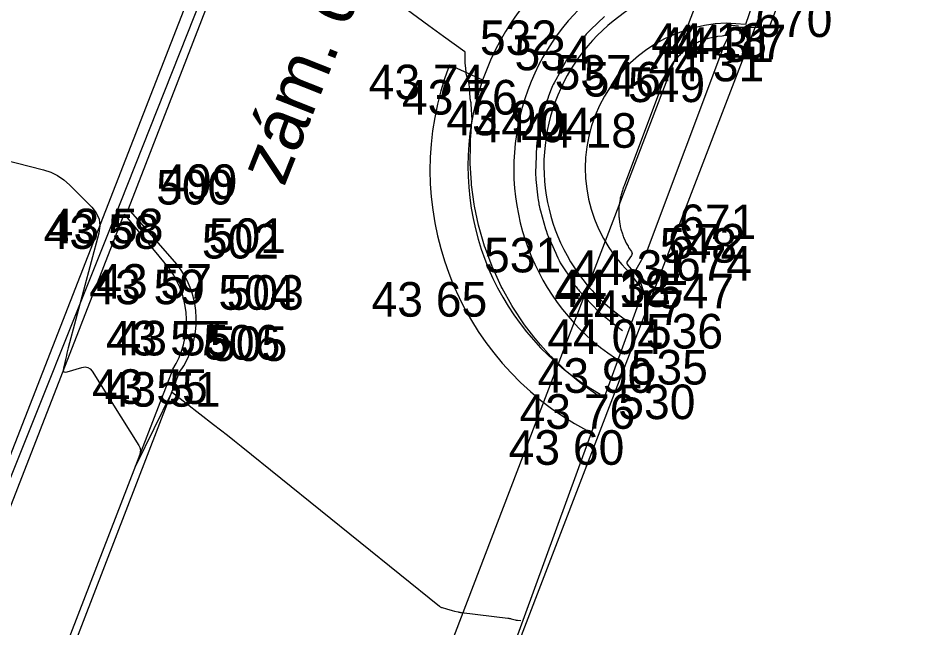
# Model space of a CAD drawing. Extents: x -702257 to -701487, y -1009871 to -1008841.
# Drawn here: x -701671.59 to -701664.97, y -1009088.46 to -1009084.05 of the extents above; entities that cross this region are included whole.
import ezdxf

# ---------------------------------------------------------------- set-up
doc = ezdxf.new("R2010")
doc.units = 0
for name, color, linetype in [('Ex_Major Contours', 7, 'Continuous'), ('Ex_Minor Contours', 7, 'Continuous'), ('Z_betonova_konstrukce', 7, 'Continuous'), ('Z_body', 7, 'Continuous'), ('Z_body_cisla', 7, 'Continuous'), ('Z_body_vysky_redukovane', 7, 'Continuous'), ('Z_budova', 7, 'Continuous'), ('Z_katastr_hranice', 7, 'Continuous'), ('Z_katastr_vnitrni_kresba', 7, 'Continuous'), ('Z_komunikace', 7, 'Continuous'), ('Z_obruba', 7, 'Continuous'), ('Z_popisy', 7, 'Continuous'), ('Z_vstupy', 7, 'Continuous')]:
    doc.layers.add(name, color=color, linetype=linetype)

# ---------------------------------------------------------------- blocks, each defined once
blk = doc.blocks.new('POINT_DISPLAY')
blk.add_line((0, 0), (0, 0))

msp = doc.modelspace()

# ---------------------------------------------------------------- linework, layer by layer
at = {"layer": 'Ex_Major Contours'}
msp.add_lwpolyline([(-701667.3501, -1009084.0429), (-701667.4478, -1009084.1354), (-701667.458, -1009084.1454), (-701667.4748, -1009084.1623), (-701667.4813, -1009084.1691), (-701667.4875, -1009084.1762), (-701667.5026, -1009084.1943), (-701667.5114, -1009084.2054), (-701667.5922, -1009084.3109), (-701667.6006, -1009084.3222), (-701667.6141, -1009084.3412), (-701667.6193, -1009084.3489), (-701667.624, -1009084.357), (-701667.6546, -1009084.413), (-701667.6634, -1009084.4291), (-701667.7136, -1009084.5217), (-701667.7192, -1009084.5325), (-701667.7245, -1009084.5434), (-701667.7294, -1009084.5544), (-701667.7339, -1009084.5657), (-701667.7538, -1009084.6171), (-701667.7601, -1009084.6336), (-701667.7662, -1009084.6501), (-701667.7803, -1009084.6891), (-701667.784, -1009084.6999), (-701667.7875, -1009084.7108), (-701667.7941, -1009084.7326), (-701667.7972, -1009084.7436), (-701667.7997, -1009084.7547), (-701667.8287, -1009084.9007), (-701667.8356, -1009084.9353), (-701667.8372, -1009084.944), (-701667.8384, -1009084.9527), (-701667.8393, -1009084.9614), (-701667.8398, -1009084.9702), (-701667.8464, -1009085.1186), (-701667.8484, -1009085.1641), (-701667.8486, -1009085.1735), (-701667.8482, -1009085.1828), (-701667.8464, -1009085.2061), (-701667.845, -1009085.22), (-701667.8302, -1009085.3521), (-701667.8284, -1009085.3661), (-701667.8248, -1009085.3894), (-701667.8232, -1009085.3987), (-701667.8212, -1009085.4079), (-701667.8156, -1009085.4311), (-701667.812, -1009085.4449), (-701667.7759, -1009085.5745), (-701667.7718, -1009085.5882), (-701667.7645, -1009085.6109), (-701667.7612, -1009085.6199), (-701667.7575, -1009085.6286), (-701667.7012, -1009085.7508), (-701667.6954, -1009085.7639), (-701667.6862, -1009085.7859), (-701667.6823, -1009085.7946), (-701667.6781, -1009085.8031), (-701667.6694, -1009085.8199), (-701667.6648, -1009085.8282), (-701667.6597, -1009085.8363), (-701667.5857, -1009085.9465), (-701667.578, -1009085.9583), (-701667.5654, -1009085.9784), (-701667.5603, -1009085.9862), (-701667.5549, -1009085.9938), (-701667.5437, -1009086.0088), (-701667.5379, -1009086.0162), (-701667.5318, -1009086.0232), (-701667.45, -1009086.1114), (-701667.4313, -1009086.1315), (-701667.3999, -1009086.1647), (-701667.3935, -1009086.1712), (-701667.3869, -1009086.1775), (-701667.3801, -1009086.1836), (-701667.373, -1009086.1894), (-701667.2895, -1009086.2558), (-701667.2687, -1009086.2722), (-701667.22, -1009086.31)], dxfattribs=at)
at = {"layer": 'Ex_Minor Contours'}
for points in [[(-701667.3863, -1009086.7863), (-701667.3962, -1009086.7807), (-701667.3986, -1009086.7792), (-701667.5071, -1009086.7018), (-701667.514, -1009086.6971), (-701667.6237, -1009086.6058), (-701667.631, -1009086.5988), (-701667.7307, -1009086.503), (-701667.7369, -1009086.4965), (-701667.8121, -1009086.4128), (-701667.8243, -1009086.399), (-701667.8362, -1009086.385), (-701667.8478, -1009086.3708), (-701667.8592, -1009086.3564), (-701667.9268, -1009086.2691), (-701667.9331, -1009086.2605), (-701668.012, -1009086.1412), (-701668.0195, -1009086.1291), (-701668.0886, -1009086.0052), (-701668.0959, -1009085.991), (-701668.1552, -1009085.863), (-701668.1616, -1009085.8475), (-701668.2105, -1009085.7171), (-701668.2162, -1009085.6997), (-701668.2552, -1009085.5659), (-701668.2594, -1009085.549), (-701668.2884, -1009085.412), (-701668.2909, -1009085.3966), (-701668.31, -1009085.2569), (-701668.3111, -1009085.244), (-701668.32, -1009085.1033), (-701668.3201, -1009085.0971), (-701668.3196, -1009085.0846), (-701668.319, -1009084.9796), (-701668.3187, -1009084.9616), (-701668.3181, -1009084.9436), (-701668.3172, -1009084.9256), (-701668.316, -1009084.9077), (-701668.3074, -1009084.7964), (-701668.3068, -1009084.7906), (-701668.3126, -1009084.6716), (-701668.3134, -1009084.6647), (-701668.3149, -1009084.6578), (-701668.319, -1009084.6443), (-701668.3206, -1009084.6375), (-701668.3214, -1009084.6305), (-701668.3261, -1009084.5485), (-701668.327, -1009084.5388), (-701668.3283, -1009084.5293), (-701668.3303, -1009084.5198), (-701668.3327, -1009084.5104), (-701668.3484, -1009084.4567), (-701668.3493, -1009084.4521), (-701668.3502, -1009084.4426), (-701668.3542, -1009084.3952), (-701668.3553, -1009084.3793), (-701668.357, -1009084.3454), (-701668.3571, -1009084.3355), (-701668.357, -1009084.3179), (-701668.3567, -1009084.3119), (-701668.356, -1009084.3039), (-701668.3566, -1009084.3003), (-701668.359, -1009084.2975), (-701668.5142, -1009084.1852), (-701668.5406, -1009084.1661), (-701668.5669, -1009084.1469), (-701668.5932, -1009084.1277), (-701668.6195, -1009084.1084), (-701669.6489, -1009083.3513)], [(-701666.3814, -1009084.1114), (-701666.4277, -1009084.1075), (-701666.4348, -1009084.1078), (-701666.441, -1009084.1099), (-701666.446, -1009084.114), (-701666.45, -1009084.12), (-701666.4732, -1009084.1663), (-701666.4775, -1009084.1731), (-701666.4831, -1009084.1782), (-701666.4898, -1009084.1815), (-701666.4977, -1009084.1832), (-701666.5316, -1009084.1866), (-701666.54, -1009084.1876), (-701666.5484, -1009084.1889), (-701666.5568, -1009084.1904), (-701666.5651, -1009084.1923), (-701666.5998, -1009084.2009), (-701666.6083, -1009084.2032), (-701666.6166, -1009084.2057), (-701666.6249, -1009084.2086), (-701666.6331, -1009084.2118), (-701666.6667, -1009084.2256), (-701666.675, -1009084.2291), (-701666.6831, -1009084.233), (-701666.691, -1009084.2372), (-701666.6988, -1009084.2416), (-701666.7302, -1009084.2604), (-701666.7379, -1009084.2652), (-701666.7454, -1009084.2703), (-701666.7527, -1009084.2757), (-701666.7598, -1009084.2813), (-701666.7881, -1009084.3046), (-701666.7949, -1009084.3104), (-701666.8015, -1009084.3165), (-701666.8078, -1009084.3228), (-701666.8139, -1009084.3294), (-701666.8382, -1009084.3564), (-701666.844, -1009084.3631), (-701666.8495, -1009084.3699), (-701666.8547, -1009084.3769), (-701666.8597, -1009084.3842), (-701666.8794, -1009084.414), (-701666.884, -1009084.4211), (-701666.8883, -1009084.4285), (-701666.8923, -1009084.4359), (-701666.8961, -1009084.4436), (-701666.9106, -1009084.4744), (-701666.9142, -1009084.4821), (-701666.9176, -1009084.4899), (-701666.9208, -1009084.4978), (-701666.9239, -1009084.5057), (-701667.2081, -1009085.2653), (-701667.211, -1009085.2733), (-701667.2138, -1009085.2814), (-701667.2165, -1009085.2894), (-701667.2191, -1009085.2976), (-701667.2292, -1009085.3301), (-701667.2315, -1009085.3383), (-701667.2336, -1009085.3465), (-701667.2354, -1009085.3548), (-701667.2369, -1009085.3632), (-701667.2425, -1009085.3985), (-701667.2437, -1009085.4072), (-701667.2446, -1009085.4159), (-701667.2451, -1009085.4246), (-701667.2454, -1009085.4334), (-701667.2458, -1009085.4698), (-701667.2457, -1009085.4787), (-701667.2453, -1009085.4877), (-701667.2445, -1009085.4966), (-701667.2434, -1009085.5055), (-701667.2383, -1009085.5418), (-701667.2369, -1009085.5507), (-701667.2351, -1009085.5596), (-701667.233, -1009085.5684), (-701667.2306, -1009085.5772), (-701667.2202, -1009085.6122), (-701667.2174, -1009085.6208), (-701667.2144, -1009085.6292), (-701667.211, -1009085.6375), (-701667.2074, -1009085.6457), (-701667.1919, -1009085.6786), (-701667.188, -1009085.6865), (-701667.1838, -1009085.6942), (-701667.1794, -1009085.7018), (-701667.1747, -1009085.7092), (-701667.1552, -1009085.7385), (-701667.1515, -1009085.7458), (-701667.1503, -1009085.7531), (-701667.1516, -1009085.7604), (-701667.1553, -1009085.7677), (-701667.1839, -1009085.8098), (-701667.1876, -1009085.8173), (-701667.1886, -1009085.8246), (-701667.1866, -1009085.8318), (-701667.1819, -1009085.8388), (-701667.1573, -1009085.8663), (-701667.1512, -1009085.8732), (-701667.1452, -1009085.8802), (-701667.1393, -1009085.8872), (-701667.1334, -1009085.8944), (-701667.0967, -1009085.94)], [(-701673.8988, -1009084.5112), (-701671.4049, -1009085.1496), (-701671.3519, -1009085.1669), (-701671.3027, -1009085.1906), (-701671.2572, -1009085.2209), (-701671.2154, -1009085.2577), (-701671.0556, -1009085.4178), (-701671.0225, -1009085.4596), (-701671.0029, -1009085.5052), (-701670.997, -1009085.5543), (-701671.0047, -1009085.6072), (-701671.225, -1009086.4359), (-701671.2298, -1009086.4542), (-701671.2344, -1009086.4725), (-701671.2388, -1009086.4909), (-701671.2431, -1009086.5093), (-701671.26, -1009086.5829), (-701671.2614, -1009086.5984), (-701671.2572, -1009086.6078), (-701671.2475, -1009086.6113), (-701671.2322, -1009086.6089), (-701671.1263, -1009086.5769), (-701671.1039, -1009086.5733), (-701671.0842, -1009086.5767), (-701671.0671, -1009086.5871), (-701671.0526, -1009086.6045), (-701670.7156, -1009087.1398), (-701670.7077, -1009087.1558), (-701670.704, -1009087.1723), (-701670.7044, -1009087.1891), (-701670.709, -1009087.2064), (-701670.7355, -1009087.2763), (-701670.7403, -1009087.2895), (-701670.7413, -1009087.2941), (-701670.7387, -1009087.2902), (-701670.7323, -1009087.2777), (-701670.4776, -1009086.7581), (-701670.4766, -1009086.7566), (-701670.4754, -1009086.7559), (-701670.474, -1009086.756), (-701670.4723, -1009086.7569), (-701670.1744, -1009086.9881), (-701670.1243, -1009087.0271), (-701670.0744, -1009087.0665), (-701670.0246, -1009087.106), (-701669.975, -1009087.1458), (-701668.5413, -1009088.3016), (-701668.5369, -1009088.3047), (-701668.5323, -1009088.3074), (-701668.5274, -1009088.3096), (-701668.5223, -1009088.3114), (-701668.491, -1009088.3203), (-701668.4506, -1009088.3314), (-701668.4333, -1009088.336), (-701668.4078, -1009088.3426), (-701668.4017, -1009088.3441), (-701668.3954, -1009088.3454), (-701668.3892, -1009088.3465), (-701668.3829, -1009088.3473), (-701668.0473, -1009088.3876), (-701668.0412, -1009088.3884), (-701668.0351, -1009088.3895), (-701668.029, -1009088.3907), (-701668.023, -1009088.3922), (-701667.9953, -1009088.3993), (-701667.9871, -1009088.401), (-701667.9787, -1009088.4019), (-701667.9533, -1009088.4033)]]:
    msp.add_lwpolyline(points, dxfattribs=at)
at = {"layer": 'Z_betonova_konstrukce'}
for p, q in [((-701665.94, -1009082.97), (-701666.33, -1009084.1)), ((-701666.33, -1009084.1), (-701666.47, -1009084.09)), ((-701668.47, -1009084.39), (-701668.23, -1009084.5)), ((-701667.17, -1009085.89), (-701667.07, -1009086.02))]:
    msp.add_line(p, q, dxfattribs=at)
for centre, radius, start, end in [((-701666.3628, -1009085.141), 1.6424, 92.34671, 236.46766), ((-701666.4452, -1009085.1201), 1.3422, 93.19281, 235.78309), ((-701666.4403, -1009085.1377), 1.0481, 91.62476, 225.87423)]:
    msp.add_arc(centre, radius, start, end, dxfattribs=at)
for centre, major_axis, ratio, start_param, end_param in [((-701666.451, -1009085.128), (-0.6622, 1.7685), 0.998356, 5.93445, 8.550797), ((-701666.4777, -1009085.1512), (-2.0888, 0.4308), 0.998282, 6.121365, 7.567806)]:
    msp.add_ellipse(centre, major_axis=major_axis, ratio=ratio, start_param=start_param, end_param=end_param, dxfattribs=at)
at = {"layer": 'Z_budova'}
for p, q in [((-701665.6, -1009082.67), (-701666.16, -1009084.12)), ((-701666.49, -1009084.26), (-701666.42, -1009084.12)), ((-701666.42, -1009084.12), (-701666.16, -1009084.12)), ((-701667.12, -1009085.87), (-701667.04, -1009085.73)), ((-701667.12, -1009085.87), (-701667.07, -1009086.02)), ((-701667.07, -1009086.02), (-701668.19, -1009089.09))]:
    msp.add_line(p, q, dxfattribs=at)
at = {"layer": 'Z_katastr_hranice'}
for p, q in [((-701665.49, -1009080.82), (-701668.63, -1009089.02)), ((-701670.9, -1009085.52), (-701669.52, -1009082.04)), ((-701673.75, -1009092.63), (-701670.9, -1009085.52))]:
    msp.add_line(p, q, dxfattribs=at)
at = {"layer": 'Z_katastr_vnitrni_kresba'}
msp.add_line((-701664.97, -1009080.76), (-701668.13, -1009088.98), dxfattribs=at)
at = {"layer": 'Z_komunikace'}
msp.add_line((-701673.36, -1009091.61), (-701669.58, -1009081.92), dxfattribs=at)
at = {"layer": 'Z_obruba'}
for p, q in [((-701670.79, -1009085.43), (-701669.44, -1009081.96)), ((-701670.44, -1009085.83), (-701670.79, -1009085.43)), ((-701673.23, -1009091.65), (-701670.82, -1009085.47)), ((-701670.82, -1009085.47), (-701670.49, -1009085.87)), ((-701670.47, -1009086.59), (-701672.7, -1009092.36)), ((-701672.65, -1009092.38), (-701670.42, -1009086.61))]:
    msp.add_line(p, q, dxfattribs=at)
for centre, major_axis, ratio, start_param, end_param in [((-701670.9498, -1009086.2297), (-0.4334, 0.4876), 0.992968, 3.364682, 4.651121), ((-701671.0172, -1009086.2447), (0.6446, -0.0586), 0.99844, 5.810363, 6.992503)]:
    msp.add_ellipse(centre, major_axis=major_axis, ratio=ratio, start_param=start_param, end_param=end_param, dxfattribs=at)
at = {"layer": 'Z_vstupy'}
msp.add_line((-701666.49, -1009084.26), (-701667.04, -1009085.73), dxfattribs=at)

# ---------------------------------------------------------------- block references
at = {"layer": 'Z_body'}
for p in [(-701666.47, -1009084.09), (-701666.42, -1009084.12), (-701666.33, -1009084.1), (-701666.49, -1009084.26), (-701668.47, -1009084.39), (-701668.23, -1009084.5), (-701667.93, -1009084.65), (-701667.72, -1009084.7), (-701667.41, -1009084.74), (-701670.79, -1009085.43), (-701670.82, -1009085.47), (-701667.04, -1009085.73), (-701670.44, -1009085.83), (-701670.49, -1009085.87), (-701667.17, -1009085.89), (-701667.12, -1009085.87), (-701668.45, -1009085.96), (-701667.07, -1009086.02), (-701670.37, -1009086.24), (-701670.3, -1009086.24), (-701667.2, -1009086.23), (-701667.27, -1009086.51), (-701670.47, -1009086.59), (-701670.42, -1009086.61), (-701667.38, -1009086.77), (-701667.48, -1009087.03)]:
    msp.add_blockref('POINT_DISPLAY', p, dxfattribs=at)

# ---------------------------------------------------------------- texts
at = {"layer": 'Z_body_cisla'}
for s, p in [('670', (-701666.26, -1009084.19)), ('532', (-701668.25, -1009084.32)), ('534', (-701668, -1009084.43)), ('537', (-701667.71, -1009084.57)), ('546', (-701667.5, -1009084.62)), ('549', (-701667.18, -1009084.66)), ('499', (-701670.56, -1009085.36)), ('500', (-701670.59, -1009085.4)), ('671', (-701666.81, -1009085.65)), ('501', (-701670.21, -1009085.75)), ('502', (-701670.26, -1009085.79)), ('548', (-701666.95, -1009085.82)), ('672', (-701666.89, -1009085.79)), ('531', (-701668.22, -1009085.89)), ('674', (-701666.84, -1009085.95)), ('504', (-701670.14, -1009086.16)), ('503', (-701670.08, -1009086.16)), ('547', (-701666.97, -1009086.15)), ('536', (-701667.05, -1009086.44)), ('506', (-701670.25, -1009086.52)), ('505', (-701670.2, -1009086.53)), ('535', (-701667.16, -1009086.7)), ('530', (-701667.25, -1009086.95))]:
    msp.add_text(s, height=0.25, dxfattribs=at).set_placement(p)
at = {"layer": 'Z_body_vysky_redukovane'}
for s, p in [('44 18', (-701667.0117, -1009084.34)), ('44 31', (-701666.9617, -1009084.37)), ('44 17', (-701666.8717, -1009084.35)), ('44 31', (-701667.0317, -1009084.51)), ('43 74', (-701669.0533, -1009084.64)), ('43 76', (-701668.8133, -1009084.75)), ('43 90', (-701668.4925, -1009084.9)), ('44 04', (-701668.2825, -1009084.95)), ('44 18', (-701667.9517, -1009084.99)), ('43 58', (-701671.3733, -1009085.68)), ('43 58', (-701671.4033, -1009085.72)), ('44 31', (-701667.5817, -1009085.98)), ('43 57', (-701671.0233, -1009086.08)), ('43 59', (-701671.0733, -1009086.12)), ('44 18', (-701667.7117, -1009086.14)), ('44 32', (-701667.7033, -1009086.12)), ('43 65', (-701669.0333, -1009086.21)), ('44 17', (-701667.6117, -1009086.27)), ('43 57', (-701670.9533, -1009086.49)), ('43 55', (-701670.8833, -1009086.49)), ('44 04', (-701667.7625, -1009086.48)), ('43 90', (-701667.8325, -1009086.76)), ('43 55', (-701671.0533, -1009086.84)), ('43 51', (-701670.9617, -1009086.86)), ('43 76', (-701667.9633, -1009087.02)), ('43 60', (-701668.0425, -1009087.28))]:
    msp.add_text(s, height=0.25, dxfattribs=at).set_placement(p)
at = {"layer": 'Z_popisy'}
msp.add_text('zám. dlažba', height=0.38, rotation=68.4, dxfattribs=at).set_placement((-701669.666, -1009085.279))

doc.saveas('drawing.dxf')
